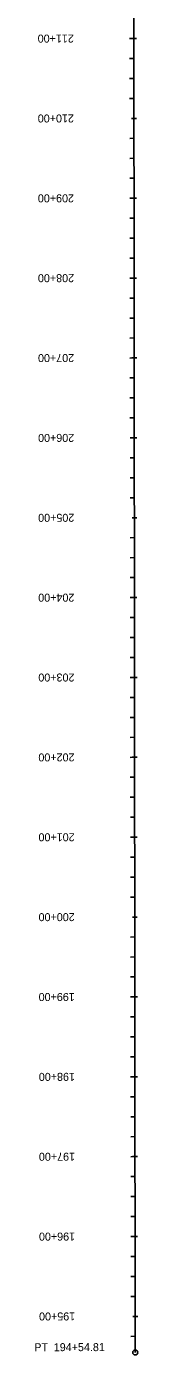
# Model space of a CAD drawing. Extents: x 23417911 to 23421158, y 6737892 to 6791804.
# Drawn here: x 23418174 to 23418302, y 6745930 to 6747590 of the extents above; entities that cross this region are included whole.
import ezdxf

# ---------------------------------------------------------------- set-up
doc = ezdxf.new("R2010")
doc.units = 0
for name, color, linetype in [('Alignment', 7, 'Continuous'), ('TextAlignment', 7, 'Continuous'), ('TextAlignmentLrg', 7, 'Continuous'), ('TextAlignmentSml', 7, 'Continuous')]:
    doc.layers.add(name, color=color, linetype=linetype)

msp = doc.modelspace()

# ---------------------------------------------------------------- linework, layer by layer
at = {"layer": 'Alignment'}
msp.add_line((23418298.6, 6745929.6), (23418296.3, 6748119.1), dxfattribs=at)
msp.add_line((23418298.6, 6745929.6), (23418296.3, 6748119.1), dxfattribs=at)
at = {"layer": 'TextAlignment'}
msp.add_circle((23418298.6, 6745929.6), 3.12, dxfattribs=at)
at = {"layer": 'TextAlignmentLrg'}
for p, q in [((23418296.9, 6747574.8), (23418291.4, 6747574.7)), ((23418293.9, 6747474.8), (23418300, 6747474.8)), ((23418297.1, 6747374.8), (23418291.6, 6747374.7)), ((23418297.2, 6747274.8), (23418291.7, 6747274.7)), ((23418297.3, 6747174.8), (23418291.8, 6747174.7)), ((23418297.4, 6747074.8), (23418292, 6747074.7)), ((23418294.5, 6746974.8), (23418300.6, 6746974.8)), ((23418297.6, 6746874.8), (23418292.2, 6746874.7)), ((23418297.7, 6746774.8), (23418292.3, 6746774.7)), ((23418297.8, 6746674.8), (23418292.4, 6746674.7)), ((23418297.9, 6746574.8), (23418292.5, 6746574.7)), ((23418295, 6746474.8), (23418301.1, 6746474.8)), ((23418298.2, 6746374.8), (23418292.7, 6746374.7)), ((23418298.3, 6746274.8), (23418292.8, 6746274.7)), ((23418298.4, 6746174.8), (23418292.9, 6746174.7)), ((23418298.5, 6746074.8), (23418293, 6746074.7)), ((23418295.5, 6745974.8), (23418301.6, 6745974.8))]:
    msp.add_line(p, q, dxfattribs=at)
at = {"layer": 'TextAlignmentSml'}
for p, q in [((23418293.8, 6747574.8), (23418299.9, 6747574.8)), ((23418296.9, 6747549.8), (23418291.4, 6747549.7)), ((23418296.9, 6747524.8), (23418291.5, 6747524.7)), ((23418297, 6747499.8), (23418291.5, 6747499.7)), ((23418293.9, 6747474.8), (23418300, 6747474.8)), ((23418297, 6747449.8), (23418291.6, 6747449.7)), ((23418297, 6747424.8), (23418291.6, 6747424.7)), ((23418297.1, 6747399.8), (23418291.6, 6747399.7)), ((23418294, 6747374.8), (23418300.2, 6747374.8)), ((23418297.1, 6747349.8), (23418291.7, 6747349.7)), ((23418297.1, 6747324.8), (23418291.7, 6747324.7)), ((23418297.2, 6747299.8), (23418291.7, 6747299.7)), ((23418294.1, 6747274.8), (23418300.3, 6747274.8)), ((23418297.2, 6747249.8), (23418291.8, 6747249.7)), ((23418297.3, 6747224.8), (23418291.8, 6747224.7)), ((23418297.3, 6747199.8), (23418291.8, 6747199.7)), ((23418294.2, 6747174.8), (23418300.4, 6747174.8)), ((23418297.3, 6747149.8), (23418291.9, 6747149.7)), ((23418297.4, 6747124.8), (23418291.9, 6747124.7)), ((23418297.4, 6747099.8), (23418291.9, 6747099.7)), ((23418294.4, 6747074.8), (23418300.5, 6747074.8)), ((23418297.4, 6747049.8), (23418292, 6747049.7)), ((23418297.5, 6747024.8), (23418292, 6747024.7)), ((23418297.5, 6746999.8), (23418292, 6746999.7)), ((23418294.5, 6746974.8), (23418300.6, 6746974.8)), ((23418297.5, 6746949.8), (23418292.1, 6746949.7)), ((23418297.6, 6746924.8), (23418292.1, 6746924.7)), ((23418297.6, 6746899.8), (23418292.1, 6746899.7)), ((23418294.6, 6746874.8), (23418300.7, 6746874.8)), ((23418297.6, 6746849.8), (23418292.2, 6746849.7)), ((23418297.7, 6746824.8), (23418292.2, 6746824.7)), ((23418297.7, 6746799.8), (23418292.2, 6746799.7)), ((23418294.7, 6746774.8), (23418300.8, 6746774.8)), ((23418297.8, 6746749.8), (23418292.3, 6746749.7)), ((23418297.8, 6746724.8), (23418292.3, 6746724.7)), ((23418297.8, 6746699.8), (23418292.3, 6746699.7)), ((23418294.8, 6746674.8), (23418300.9, 6746674.8)), ((23418297.9, 6746649.8), (23418292.4, 6746649.7)), ((23418297.9, 6746624.8), (23418292.4, 6746624.7)), ((23418297.9, 6746599.8), (23418292.5, 6746599.7)), ((23418294.9, 6746574.8), (23418301, 6746574.8)), ((23418298, 6746549.8), (23418292.5, 6746549.7)), ((23418298, 6746524.8), (23418292.5, 6746524.7)), ((23418298, 6746499.8), (23418292.6, 6746499.7)), ((23418295, 6746474.8), (23418301.1, 6746474.8)), ((23418298.1, 6746449.8), (23418292.6, 6746449.7)), ((23418298.1, 6746424.8), (23418292.6, 6746424.7)), ((23418298.1, 6746399.8), (23418292.7, 6746399.7)), ((23418295.1, 6746374.8), (23418301.2, 6746374.8)), ((23418298.2, 6746349.8), (23418292.7, 6746349.7)), ((23418298.2, 6746324.8), (23418292.7, 6746324.7)), ((23418298.2, 6746299.8), (23418292.8, 6746299.7)), ((23418295.2, 6746274.8), (23418301.3, 6746274.8)), ((23418298.3, 6746249.8), (23418292.8, 6746249.7)), ((23418298.3, 6746224.8), (23418292.9, 6746224.7)), ((23418298.3, 6746199.8), (23418292.9, 6746199.7)), ((23418295.3, 6746174.8), (23418301.4, 6746174.8)), ((23418298.4, 6746149.8), (23418292.9, 6746149.7)), ((23418298.4, 6746124.8), (23418293, 6746124.7)), ((23418298.4, 6746099.8), (23418293, 6746099.7)), ((23418295.4, 6746074.8), (23418301.5, 6746074.8)), ((23418298.5, 6746049.8), (23418293, 6746049.7)), ((23418298.5, 6746024.8), (23418293.1, 6746024.7)), ((23418298.5, 6745999.8), (23418293.1, 6745999.7)), ((23418295.5, 6745974.8), (23418301.6, 6745974.8)), ((23418298.6, 6745949.8), (23418293.1, 6745949.7))]:
    msp.add_line(p, q, dxfattribs=at)

# ---------------------------------------------------------------- texts
at = {"layer": 'TextAlignment'}
for s, p in [('PT', (23418172.6, 6745931.1)), ('194+54.81', (23418196.9, 6745931.2))]:
    msp.add_text(s, height=10.02, rotation=0.0607, dxfattribs=at).set_placement(p)
at = {"layer": 'TextAlignmentLrg'}
for s, p in [('210+00', (23418222, 6747479.7)), ('205+00', (23418222.5, 6746979.7)), ('200+00', (23418223, 6746479.7)), ('195+00', (23418223.6, 6745979.7))]:
    msp.add_text(s, height=10.02, rotation=180.0607, dxfattribs=at).set_placement(p)
at = {"layer": 'TextAlignmentSml'}
for s, p in [('211+00', (23418221.9, 6747579.7)), ('210+00', (23418222, 6747479.7)), ('209+00', (23418222.1, 6747379.7)), ('208+00', (23418222.2, 6747279.7)), ('207+00', (23418222.3, 6747179.7)), ('206+00', (23418222.4, 6747079.7)), ('205+00', (23418222.5, 6746979.7)), ('204+00', (23418222.6, 6746879.7)), ('203+00', (23418222.7, 6746779.7)), ('202+00', (23418222.8, 6746679.7)), ('201+00', (23418222.9, 6746579.7)), ('200+00', (23418223, 6746479.7)), ('199+00', (23418223.1, 6746379.7)), ('198+00', (23418223.3, 6746279.7)), ('197+00', (23418223.4, 6746179.7)), ('196+00', (23418223.5, 6746079.7)), ('195+00', (23418223.6, 6745979.7))]:
    msp.add_text(s, height=10.02, rotation=180.0607, dxfattribs=at).set_placement(p)

doc.saveas('drawing.dxf')
